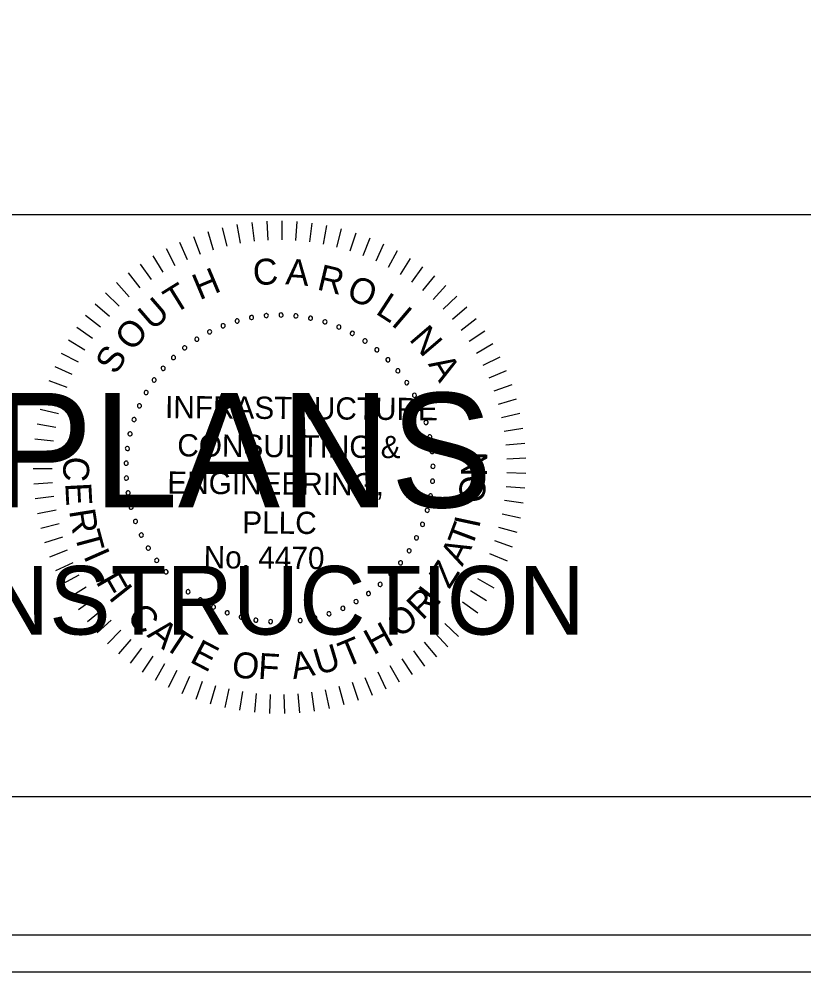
# Model space of a CAD drawing. Extents: x 967 to 1623, y 964 to 7064.
# Drawn here: x 1189.3 to 1212.88, y 6843.72 to 6872.36 of the extents above; entities that cross this region are included whole.
import ezdxf

# ---------------------------------------------------------------- set-up
doc = ezdxf.new("R2010")
doc.units = 0
for name, color, linetype in [('RD_SHT_Bndy', 7, 'Continuous'), ('RD_SHT_IplotShp', 7, 'Continuous'), ('RD_SHT_Misc1', 7, 'Continuous'), ('RD_SHT_Misc2', 7, 'Continuous'), ('RD_Sketch1', 7, 'Continuous')]:
    doc.layers.add(name, color=color, linetype=linetype)

msp = doc.modelspace()

# ---------------------------------------------------------------- linework, layer by layer
at = {"layer": 'RD_SHT_Bndy'}
for p, q in [((996.114, 6866.486), (1323.886, 6866.486)), ((1323.886, 6848.983), (996.114, 6848.983))]:
    msp.add_line(p, q, dxfattribs=at)
at = {"layer": 'RD_SHT_IplotShp'}
for points in [[(967.409, 6843.72), (1326.285, 6843.72), (1326.285, 7063.72), (967.409, 7063.72)], [(988.525, 6844.84), (1326.285, 6844.84), (1326.285, 7062.6), (988.525, 7062.6)]]:
    msp.add_lwpolyline(points, close=True, dxfattribs=at)
at = {"layer": 'RD_SHT_Misc1'}
for p, q in [((1195.846, 6866.181), (1195.945, 6865.62)), ((1196.292, 6866.245), (1196.357, 6865.68)), ((1196.742, 6866.282), (1196.772, 6865.714)), ((1197.194, 6866.292), (1197.189, 6865.723)), ((1197.645, 6866.274), (1197.606, 6865.706)), ((1198.094, 6866.228), (1198.02, 6865.664)), ((1198.54, 6866.156), (1198.432, 6865.596)), ((1194.54, 6865.827), (1194.739, 6865.293)), ((1194.968, 6865.971), (1195.134, 6865.427)), ((1195.403, 6866.09), (1195.536, 6865.536)), ((1198.98, 6866.056), (1198.838, 6865.504)), ((1199.414, 6865.929), (1199.238, 6865.387)), ((1194.122, 6865.656), (1194.353, 6865.136)), ((1199.839, 6865.777), (1199.63, 6865.246)), ((1200.253, 6865.598), (1200.013, 6865.082)), ((1193.321, 6865.241), (1193.614, 6864.752)), ((1193.715, 6865.461), (1193.978, 6864.956)), ((1200.656, 6865.395), (1200.385, 6864.894)), ((1192.94, 6864.997), (1193.263, 6864.528)), ((1201.047, 6865.167), (1200.745, 6864.684)), ((1192.576, 6864.731), (1192.926, 6864.282)), ((1201.422, 6864.917), (1201.092, 6864.453)), ((1192.228, 6864.443), (1192.605, 6864.016)), ((1201.781, 6864.643), (1201.424, 6864.2)), ((1191.899, 6864.134), (1192.301, 6863.731)), ((1202.124, 6864.349), (1201.739, 6863.928)), ((1191.589, 6863.805), (1192.015, 6863.428)), ((1202.447, 6864.034), (1202.038, 6863.638)), ((1202.751, 6863.7), (1202.318, 6863.329)), ((1191.299, 6863.459), (1191.748, 6863.108)), ((1203.034, 6863.348), (1202.579, 6863.004)), ((1191.032, 6863.095), (1191.501, 6862.772)), ((1203.294, 6862.979), (1202.82, 6862.664)), ((1190.787, 6862.716), (1191.274, 6862.422)), ((1203.532, 6862.595), (1203.04, 6862.31)), ((1190.565, 6862.323), (1191.07, 6862.059)), ((1203.746, 6862.198), (1203.237, 6861.943)), ((1190.368, 6861.916), (1190.888, 6861.684)), ((1203.936, 6861.788), (1203.412, 6861.564)), ((1190.196, 6861.499), (1190.729, 6861.299)), ((1204.1, 6861.367), (1203.563, 6861.176)), ((1190.05, 6861.072), (1190.594, 6860.905)), ((1204.238, 6860.937), (1203.691, 6860.779)), ((1189.93, 6860.636), (1190.484, 6860.503)), ((1204.349, 6860.5), (1203.794, 6860.375)), ((1189.837, 6860.195), (1190.398, 6860.095)), ((1204.434, 6860.056), (1203.872, 6859.966)), ((1189.771, 6859.748), (1190.337, 6859.683)), ((1204.491, 6859.608), (1203.925, 6859.552)), ((1189.732, 6859.298), (1190.301, 6859.267)), ((1204.522, 6859.158), (1203.953, 6859.137)), ((1189.721, 6858.847), (1190.29, 6858.851)), ((1204.524, 6858.706), (1203.955, 6858.72)), ((1189.737, 6858.396), (1190.306, 6858.434)), ((1204.499, 6858.256), (1203.932, 6858.304)), ((1189.781, 6857.946), (1190.346, 6858.019)), ((1204.447, 6857.807), (1203.884, 6857.89)), ((1189.852, 6857.5), (1190.412, 6857.608)), ((1204.367, 6857.363), (1203.81, 6857.479)), ((1189.951, 6857.06), (1190.502, 6857.201)), ((1204.261, 6856.924), (1203.712, 6857.074)), ((1190.076, 6856.626), (1190.617, 6856.8)), ((1204.128, 6856.492), (1203.589, 6856.676)), ((1190.227, 6856.2), (1190.757, 6856.408)), ((1203.969, 6856.07), (1203.442, 6856.286)), ((1190.403, 6855.785), (1190.92, 6856.024)), ((1203.784, 6855.658), (1203.271, 6855.906)), ((1190.605, 6855.381), (1191.106, 6855.651)), ((1203.574, 6855.258), (1203.078, 6855.537)), ((1190.831, 6854.99), (1191.315, 6855.291)), ((1191.081, 6854.614), (1191.545, 6854.943)), ((1203.341, 6854.871), (1202.862, 6855.18)), ((1203.085, 6854.5), (1202.626, 6854.837)), ((1191.353, 6854.253), (1191.796, 6854.61)), ((1202.806, 6854.145), (1202.368, 6854.509)), ((1191.646, 6853.91), (1192.067, 6854.293)), ((1202.506, 6853.807), (1202.092, 6854.197)), ((1191.96, 6853.585), (1192.356, 6853.994)), ((1202.186, 6853.488), (1201.796, 6853.903)), ((1192.293, 6853.28), (1192.664, 6853.712)), ((1201.847, 6853.19), (1201.484, 6853.628)), ((1192.644, 6852.996), (1192.988, 6853.45)), ((1201.491, 6852.912), (1201.155, 6853.372)), ((1193.011, 6852.734), (1193.327, 6853.208)), ((1193.394, 6852.495), (1193.68, 6852.987)), ((1200.731, 6852.425), (1200.453, 6852.922)), ((1201.119, 6852.657), (1200.811, 6853.136)), ((1193.791, 6852.279), (1194.047, 6852.788)), ((1200.331, 6852.217), (1200.083, 6852.73)), ((1194.2, 6852.088), (1194.424, 6852.612)), ((1194.62, 6851.923), (1194.812, 6852.459)), ((1199.495, 6851.877), (1199.312, 6852.416)), ((1199.918, 6852.034), (1199.702, 6852.561)), ((1195.05, 6851.783), (1195.208, 6852.33)), ((1195.487, 6851.67), (1195.612, 6852.225)), ((1195.93, 6851.584), (1196.021, 6852.146)), ((1196.377, 6851.524), (1196.434, 6852.091)), ((1197.73, 6851.512), (1197.683, 6852.079)), ((1198.179, 6851.562), (1198.097, 6852.126)), ((1198.624, 6851.64), (1198.508, 6852.198)), ((1199.063, 6851.745), (1198.913, 6852.295)), ((1196.828, 6851.493), (1196.85, 6852.062)), ((1197.279, 6851.488), (1197.267, 6852.058))]:
    msp.add_line(p, q, dxfattribs=at)
for centre, start, end in [((1197.172, 6863.464), 359.5268, 179.5268), ((1195.851, 6863.285), 16.1422, 196.1422), ((1195.851, 6863.285), 196.1422, 16.1422), ((1196.285, 6863.388), 10.6038, 190.6038), ((1196.285, 6863.388), 190.6038, 10.6038), ((1196.727, 6863.447), 5.0653, 185.0653), ((1196.727, 6863.447), 185.0653, 5.0653), ((1197.172, 6863.464), 179.5268, 359.5268), ((1197.617, 6863.438), 173.9884, 353.9884), ((1197.617, 6863.438), 353.9884, 173.9884), ((1198.057, 6863.369), 168.4499, 348.4499), ((1198.057, 6863.369), 348.4499, 168.4499), ((1198.489, 6863.258), 162.9114, 342.9114), ((1198.489, 6863.258), 342.9114, 162.9114), ((1195.023, 6862.958), 27.2191, 207.2191), ((1195.023, 6862.958), 207.2191, 27.2191), ((1195.429, 6863.142), 21.6807, 201.6807), ((1195.429, 6863.142), 201.6807, 21.6807), ((1198.908, 6863.106), 157.373, 337.373), ((1198.908, 6863.106), 337.373, 157.373), ((1199.31, 6862.914), 331.8345, 151.8345), ((1194.637, 6862.736), 32.7576, 212.7576), ((1194.637, 6862.736), 212.7576, 32.7576), ((1199.31, 6862.914), 151.8345, 331.8345), ((1199.692, 6862.684), 146.2961, 326.2961), ((1199.692, 6862.684), 326.2961, 146.2961), ((1194.274, 6862.478), 38.2961, 218.2961), ((1194.274, 6862.478), 218.2961, 38.2961), ((1200.05, 6862.419), 140.7576, 320.7576), ((1200.05, 6862.419), 320.7576, 140.7576), ((1193.937, 6862.186), 43.8345, 223.8345), ((1193.937, 6862.186), 223.8345, 43.8345), ((1200.38, 6862.12), 135.2191, 315.2191), ((1200.38, 6862.12), 315.2191, 135.2191), ((1193.63, 6861.862), 49.373, 229.373), ((1193.63, 6861.862), 229.373, 49.373), ((1200.68, 6861.79), 129.6807, 309.6807), ((1200.68, 6861.79), 309.6807, 129.6807), ((1193.356, 6861.511), 54.9114, 234.9114), ((1193.356, 6861.511), 234.9114, 54.9114), ((1200.947, 6861.433), 124.1422, 304.1422), ((1200.947, 6861.433), 304.1422, 124.1422), ((1193.117, 6861.135), 60.4499, 240.4499), ((1193.117, 6861.135), 240.4499, 60.4499), ((1201.179, 6861.052), 118.6038, 298.6038), ((1201.179, 6861.052), 298.6038, 118.6038), ((1192.915, 6860.737), 65.9884, 245.9884), ((1192.915, 6860.737), 245.9884, 65.9884), ((1201.372, 6860.651), 113.0653, 293.0653), ((1201.372, 6860.651), 293.0653, 113.0653), ((1192.753, 6860.322), 71.5268, 251.5268), ((1192.753, 6860.322), 251.5268, 71.5268), ((1201.526, 6860.233), 107.5268, 287.5268), ((1201.526, 6860.233), 287.5268, 107.5268), ((1192.632, 6859.894), 77.0653, 257.0653), ((1192.632, 6859.894), 257.0653, 77.0653), ((1201.638, 6859.801), 101.9884, 281.9884), ((1201.638, 6859.801), 281.9884, 101.9884), ((1192.552, 6859.455), 82.6038, 262.6038), ((1192.552, 6859.455), 262.6038, 82.6038), ((1201.709, 6859.361), 96.4499, 276.4499), ((1201.709, 6859.361), 276.4499, 96.4499), ((1192.515, 6859.011), 88.1422, 268.1422), ((1192.515, 6859.011), 268.1422, 88.1422), ((1201.737, 6858.917), 90.9114, 270.9114), ((1201.737, 6858.917), 270.9114, 90.9114), ((1192.522, 6858.565), 93.6807, 273.6807), ((1192.522, 6858.565), 273.6807, 93.6807), ((1201.721, 6858.471), 85.373, 265.373), ((1201.721, 6858.471), 265.373, 85.373), ((1192.571, 6858.122), 99.2191, 279.2191), ((1192.571, 6858.122), 279.2191, 99.2191), ((1201.663, 6858.029), 79.8345, 259.8345), ((1201.663, 6858.029), 259.8345, 79.8345), ((1192.662, 6857.686), 104.7576, 284.7576), ((1192.662, 6857.686), 284.7576, 104.7576), ((1201.563, 6857.595), 74.2961, 254.2961), ((1201.563, 6857.595), 254.2961, 74.2961), ((1192.796, 6857.261), 110.2961, 290.2961), ((1192.796, 6857.261), 290.2961, 110.2961), ((1201.42, 6857.173), 68.7576, 248.7576), ((1201.42, 6857.173), 248.7576, 68.7576), ((1192.97, 6856.851), 115.8345, 295.8345), ((1192.97, 6856.851), 295.8345, 115.8345), ((1201.238, 6856.766), 63.2191, 243.2191), ((1201.238, 6856.766), 243.2191, 63.2191), ((1193.182, 6856.459), 121.373, 301.373), ((1193.182, 6856.459), 301.373, 121.373), ((1201.018, 6856.379), 57.6807, 237.6807), ((1201.018, 6856.379), 237.6807, 57.6807), ((1193.432, 6856.09), 126.9114, 306.9114), ((1193.432, 6856.09), 306.9114, 126.9114), ((1200.761, 6856.014), 52.1422, 232.1422), ((1193.715, 6855.746), 132.4499, 312.4499), ((1193.715, 6855.746), 312.4499, 132.4499), ((1200.761, 6856.014), 232.1422, 52.1422), ((1200.47, 6855.677), 46.6038, 226.6038), ((1200.47, 6855.677), 226.6038, 46.6038), ((1194.031, 6855.431), 137.9884, 317.9884), ((1194.031, 6855.431), 317.9884, 137.9884), ((1200.148, 6855.369), 41.0653, 221.0653), ((1200.148, 6855.369), 221.0653, 41.0653), ((1194.376, 6855.149), 143.5268, 323.5268), ((1194.376, 6855.149), 323.5268, 143.5268), ((1194.746, 6854.901), 149.0653, 329.0653), ((1194.746, 6854.901), 329.0653, 149.0653), ((1199.798, 6855.093), 35.5268, 215.5268), ((1199.798, 6855.093), 215.5268, 35.5268), ((1195.139, 6854.69), 154.6038, 334.6038), ((1195.139, 6854.69), 334.6038, 154.6038), ((1199.026, 6854.65), 24.4499, 204.4499), ((1199.026, 6854.65), 204.4499, 24.4499), ((1199.422, 6854.853), 29.9884, 209.9884), ((1199.422, 6854.853), 209.9884, 29.9884), ((1195.55, 6854.517), 160.1422, 340.1422), ((1195.55, 6854.517), 340.1422, 160.1422), ((1195.975, 6854.386), 165.6807, 345.6807), ((1195.975, 6854.386), 345.6807, 165.6807), ((1196.412, 6854.295), 351.2191, 171.2191), ((1198.183, 6854.363), 13.373, 193.373), ((1198.183, 6854.363), 193.373, 13.373), ((1198.611, 6854.486), 18.9114, 198.9114), ((1198.611, 6854.486), 198.9114, 18.9114), ((1196.412, 6854.295), 171.2191, 351.2191), ((1196.855, 6854.248), 356.7576, 176.7576), ((1196.855, 6854.248), 176.7576, 356.7576), ((1197.301, 6854.243), 2.2961, 182.2961), ((1197.301, 6854.243), 182.2961, 2.2961), ((1197.745, 6854.282), 7.8345, 187.8345), ((1197.745, 6854.282), 187.8345, 7.8345)]:
    msp.add_arc(centre, 0.0627, start, end, dxfattribs=at)
at = {"layer": 'RD_Sketch1'}
msp.add_lwpolyline([(967.409, 6843.72), (1326.285, 6843.72), (1326.285, 7063.72), (967.409, 7063.72)], close=True, dxfattribs=at)

# ---------------------------------------------------------------- texts
at = {"layer": 'RD_SHT_Misc1'}
for s, height, rotation, p in [('C', 0.78, 4.7281, (1196.355, 6864.346)), ('A', 0.78, 355.6981, (1197.29, 6864.39)), ('R', 0.78, 346.6681, (1198.222, 6864.238)), ('H', 0.78, 22.7882, (1194.72, 6863.904)), ('T', 0.78, 31.8182, (1193.961, 6863.478)), ('O', 0.78, 337.638, (1199.096, 6863.972)), ('L', 0.78, 327.108, (1199.981, 6863.52)), ('U', 0.78, 40.8482, (1193.306, 6862.976)), ('I', 0.78, 319.578, (1200.451, 6863.182)), ('O', 0.78, 49.8782, (1192.707, 6862.341)), ('N', 0.78, 310.548, (1200.994, 6862.728)), ('S', 0.78, 58.9083, (1192.211, 6861.642)), ('A', 0.78, 301.5179, (1201.576, 6861.991)), ('INFRASTRUCTURE', 0.66873, 359.5268, (1193.682, 6860.367)), ('CONSULTING &', 0.66873, 359.5268, (1194.051, 6859.217)), ('N', 0.78, 89.2085, (1203.359, 6858.604)), ('C', 0.78, 267.025, (1190.646, 6859.227)), ('ENGINEERING,', 0.66873, 359.5268, (1193.751, 6858.095)), ('E', 0.78, 273.025, (1190.685, 6858.408)), ('O', 0.78, 83.2085, (1203.26, 6857.786)), ('R', 0.78, 279.025, (1190.799, 6857.583)), ('PLLC', 0.6687, 359.5268, (1196.002, 6856.9)), ('T', 0.78, 69.3954, (1202.891, 6856.428)), ('I', 0.78, 77.9093, (1203.121, 6857.032)), ('T', 0.78, 285.025, (1190.955, 6856.878)), ('I', 0.78, 293.7713, (1191.221, 6856.225)), ('No. 4470', 0.6687, 359.5268, (1194.843, 6855.855)), ('A', 0.78, 63.3954, (1202.616, 6855.888)), ('Z', 0.78, 57.3954, (1202.224, 6855.206)), ('F', 0.78, 299.7713, (1191.589, 6855.455)), ('I', 0.78, 308.5268, (1191.965, 6854.973)), ('R', 0.78, 44.5268, (1201.415, 6854.267)), ('I', 0.78, 52.3339, (1201.856, 6854.69)), ('C', 0.78, 314.5268, (1192.496, 6854.346)), ('O', 0.78, 38.5268, (1200.73, 6853.731)), ('A', 0.78, 320.5268, (1193.115, 6853.822)), ('T', 0.78, 326.5268, (1193.602, 6853.478)), ('H', 0.78, 28.5268, (1199.942, 6853.23)), ('T', 0.78, 22.5268, (1199.108, 6852.856)), ('E', 0.78, 332.5268, (1194.394, 6853.051)), ('U', 0.78, 16.5268, (1198.288, 6852.638)), ('O', 0.78, 350.5268, (1195.647, 6852.614)), ('F', 0.78, 356.5268, (1196.465, 6852.532)), ('A', 0.78, 10.5268, (1197.537, 6852.517))]:
    msp.add_text(s, height=height, rotation=rotation, dxfattribs=at).set_placement(p)
at = {"layer": 'RD_SHT_Misc2'}
for s, height, p in [('FINAL PLANS', 3.4375, (1174.145, 6857.685)), ('NOT FOR CONSTRUCTION', 2.0625, (1170.901, 6853.86))]:
    msp.add_text(s, height=height, dxfattribs=at).set_placement(p)

doc.saveas('drawing.dxf')
